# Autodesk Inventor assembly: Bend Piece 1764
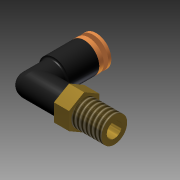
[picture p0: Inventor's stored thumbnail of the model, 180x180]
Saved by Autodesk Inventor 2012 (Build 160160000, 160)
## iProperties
Created: 2010-02
Part Number: Bend Piece 1764
Document SubType Name: Assembly
Designer: jgehrig
Author: jgehrig
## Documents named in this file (4)
- R:\CAD Archives\Pneumatics_1764\Air_Release_1764\Pneumatics_Bend_Piece_1764\Pneumatic_Bend_Piece_1764.iam
- R:\CAD Archives\Pneumatics_1764\Air_Release_1764\Pneumatics_Bend_Piece_1764\Pneumatic_Screw_Part_2_1764.ipt
- R:\CAD Archives\Pneumatics_1764\Air_Release_1764\Pneumatics_Bend_Piece_1764\Pneumatic_Screw_Part_1764.ipt
- R:\CAD Archives\Pneumatics_1764\Air_Release_1764\Pneumatics_Bend_Piece_1764\Pneumatic_Bend_Piece_1764.ipt
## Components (3 placed, 3 different names)
1. Pneumatic_Bend_Piece_1764:1 — Insert:1, Insert:2
2. Pneumatic_Screw_Part_1764:1 — Insert:2
3. Pneumatic_Screw_Part_2_1764:1 — Insert:1
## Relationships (2: Insert 2)
- Insert:1: Pneumatic_Bend_Piece_1764:1 ↔ Pneumatic_Screw_Part_2_1764:1
- Insert:2: Pneumatic_Bend_Piece_1764:1 ↔ Pneumatic_Screw_Part_1764:1
